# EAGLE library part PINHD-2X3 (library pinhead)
PIN HEADER
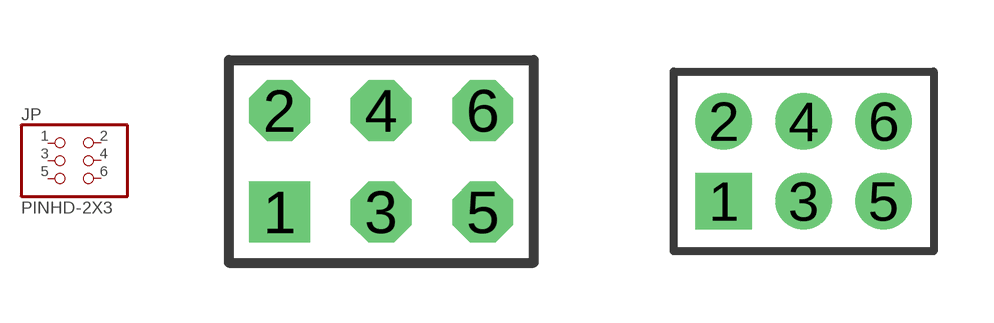
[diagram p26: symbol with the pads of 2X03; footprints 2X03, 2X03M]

Designator prefix JP

## PINHD-2X3  [2X03]
1  1  pas
2  2  pas
3  3  pas
4  4  pas
5  5  pas
6  6  pas

## PINHD-2X3M  [2X03M]
Pads as for 2X03

## Footprint 2X03 (pad centres in mm)
PIN HEADER - 0.1"
drill 1.016 square: 1 -2.54,-1.27
drill 1.016 octagon: 2 -2.54,1.27; 3 0,-1.27; 4 0,1.27; 5 2.54,-1.27; 6 2.54,1.27

## Footprint 2X03M (pad centres in mm)
PIN HEADER - 2MM"
drill 0.914 square: 1 -2,-1
drill 0.914 round: 2 -2,1; 3 0,-1; 4 0,1; 5 2,-1; 6 2,1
